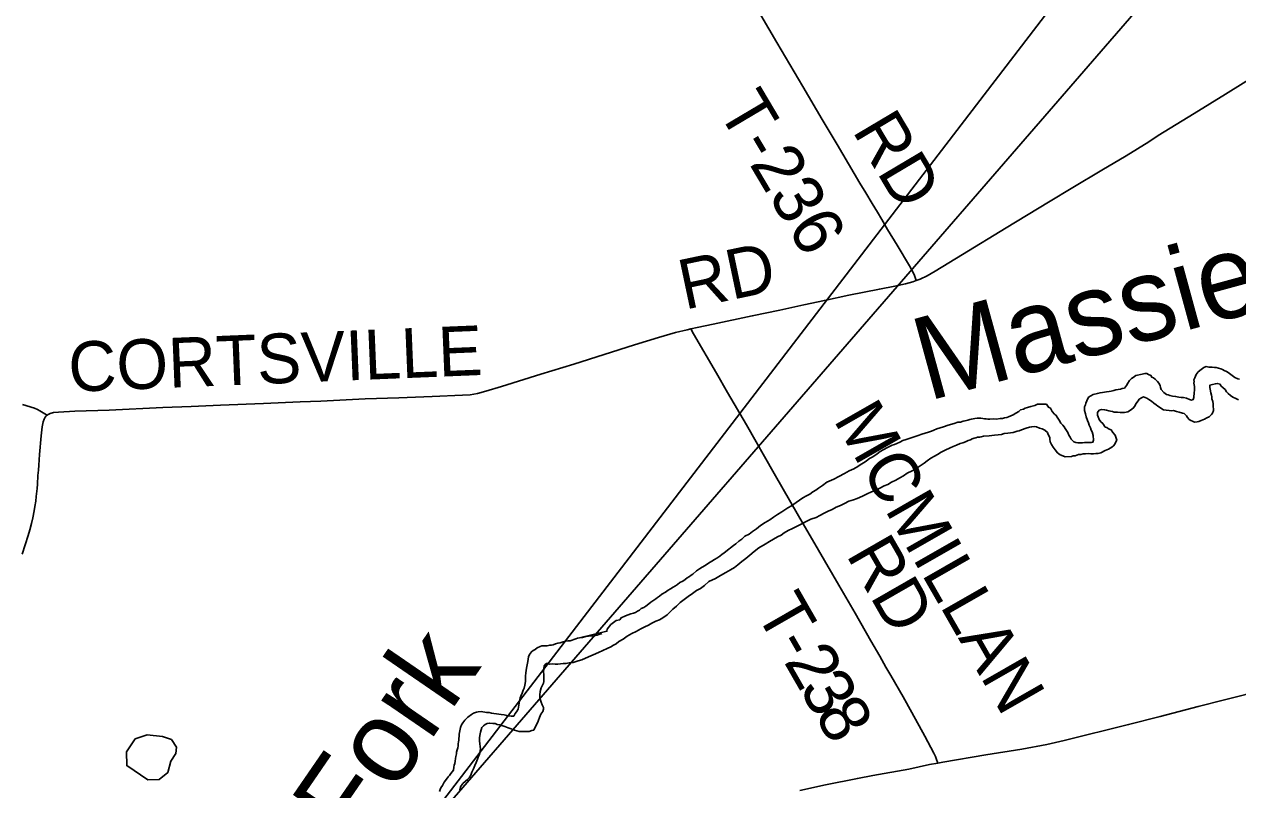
# Model space of a CAD drawing. Extents: x -19.5 to 44.1, y 0 to 22.
# Drawn here: x 5.315 to 6.7, y 19.626 to 20.5 of the extents above; entities that cross this region are included whole.
import ezdxf

# ---------------------------------------------------------------- set-up
doc = ezdxf.new("R2010")
doc.units = 0
for name, color, linetype in [('GM_X_County_Road', 7, 'Continuous'), ('GM_X_County_Road_Text', 7, 'Continuous'), ('GM_X_Minor_Lake', 7, 'Continuous'), ('GM_X_Minor_River', 7, 'Continuous'), ('GM_X_Minor_River_Text', 7, 'Continuous'), ('GM_X_Township_Road', 7, 'Continuous'), ('GM_X_Township_Road_Text', 7, 'Continuous'), ('GM_X_US_Route', 7, 'Continuous'), ('SH_Text', 7, 'Continuous')]:
    doc.layers.add(name, color=color, linetype=linetype)

msp = doc.modelspace()

# ---------------------------------------------------------------- linework, layer by layer
at = {"layer": 'GM_X_County_Road'}
for points in [[(6.3333, 20.2074), (6.338, 20.2091), (6.3458, 20.2128), (6.3549, 20.218), (6.3861, 20.2373), (6.436, 20.2676), (6.4844, 20.297), (6.5121, 20.3135), (6.5452, 20.3333), (6.5729, 20.3499), (6.5987, 20.366), (6.6097, 20.3729), (6.6505, 20.398), (6.6864, 20.4202), (6.7406, 20.4542)], [(6.076, 20.1522), (6.0834, 20.154), (6.1017, 20.1578), (6.1461, 20.167), (6.1776, 20.1737), (6.2049, 20.1797), (6.2286, 20.1848), (6.2566, 20.1906), (6.2913, 20.1976), (6.309, 20.2011), (6.3211, 20.2035), (6.3294, 20.2059), (6.3333, 20.2074)], [(5.3413, 20.0537), (5.3425, 20.0546), (5.3449, 20.0557), (5.3487, 20.0567), (5.3544, 20.0573), (5.373, 20.0582), (5.4121, 20.0596), (5.4736, 20.0624), (5.5059, 20.0637), (5.5394, 20.0651), (5.5884, 20.0672), (5.63, 20.069), (5.6536, 20.0699), (5.7044, 20.0723), (5.7429, 20.0735), (5.7808, 20.0751), (5.8155, 20.0764), (5.8241, 20.0771), (5.8326, 20.0786), (5.8422, 20.081), (5.86, 20.0863), (5.905, 20.1005), (5.9424, 20.112), (6.0117, 20.1339), (6.039, 20.1425), (6.0587, 20.148), (6.0719, 20.1513), (6.076, 20.1522)], [(5.3413, 20.0537), (5.3388, 20.0552), (5.3331, 20.0586), (5.3304, 20.0602), (5.3268, 20.0618), (5.3132, 20.0659)], [(5.3127, 19.8951), (5.3198, 19.9163), (5.3217, 19.9228), (5.3236, 19.93), (5.3251, 19.9366), (5.3266, 19.9444), (5.3274, 19.9493), (5.3283, 19.9554), (5.3288, 19.9609), (5.3298, 19.9701), (5.3302, 19.975), (5.3309, 19.9849), (5.3315, 19.991), (5.3318, 19.9966), (5.3323, 20.0027), (5.3326, 20.0089), (5.3345, 20.03), (5.3356, 20.0405), (5.3367, 20.0461), (5.3378, 20.0492), (5.3391, 20.0515), (5.3404, 20.053), (5.3413, 20.0537)]]:
    msp.add_lwpolyline(points, dxfattribs=at)
at = {"layer": 'GM_X_Minor_Lake'}
for points in [[(5.4556, 19.6888), (5.4419, 19.6841), (5.4321, 19.6695), (5.4322, 19.6536), (5.4562, 19.6375), (5.4691, 19.6376), (5.4791, 19.6458), (5.4824, 19.6586), (5.4882, 19.6673), (5.4891, 19.6748), (5.4832, 19.6833)], [(5.4832, 19.6833), (5.4731, 19.687), (5.4556, 19.6888)]]:
    msp.add_lwpolyline(points, dxfattribs=at)
at = {"layer": 'GM_X_Minor_River'}
for points in [[(6.5711, 20.0847), (6.5734, 20.0877), (6.5749, 20.0903), (6.5769, 20.0933), (6.5792, 20.0956), (6.5811, 20.0967), (6.5841, 20.0989), (6.5914, 20.1007), (6.5944, 20.1014), (6.5967, 20.1014), (6.5986, 20.1002), (6.6012, 20.099), (6.6023, 20.0971), (6.6042, 20.0963), (6.6061, 20.0948), (6.6087, 20.0921), (6.6102, 20.0902), (6.6117, 20.0875), (6.6121, 20.0852), (6.6128, 20.0829), (6.6158, 20.0798), (6.6192, 20.0775), (6.6211, 20.0771), (6.623, 20.0763), (6.626, 20.0755), (6.6294, 20.0751), (6.6332, 20.0743), (6.6358, 20.0739), (6.6385, 20.0738), (6.6419, 20.073), (6.6453, 20.0718), (6.6476, 20.071), (6.6495, 20.0718), (6.6503, 20.074), (6.6507, 20.0797), (6.6511, 20.082), (6.6508, 20.0843), (6.6508, 20.0866), (6.6501, 20.0904), (6.6505, 20.0923), (6.6501, 20.0942), (6.6513, 20.0964), (6.6529, 20.1002), (6.6552, 20.1032), (6.6586, 20.1058), (6.6617, 20.1081), (6.6644, 20.1092), (6.6674, 20.1087), (6.6712, 20.1087), (6.6739, 20.1083), (6.6758, 20.1082), (6.6784, 20.1074), (6.6811, 20.1066), (6.6829, 20.1059), (6.6848, 20.1047), (6.6875, 20.1035), (6.6893, 20.1023), (6.6969, 20.0969), (6.7003, 20.0953), (6.7022, 20.0949)], [(6.3434, 20.0332), (6.3472, 20.0343), (6.3506, 20.0354), (6.3533, 20.0365), (6.3567, 20.038), (6.3605, 20.0391), (6.3644, 20.0405), (6.3697, 20.0423), (6.3765, 20.0441), (6.3807, 20.0456), (6.3838, 20.0459), (6.3868, 20.0467), (6.3891, 20.0474), (6.3922, 20.0481), (6.3944, 20.0488), (6.3964, 20.0492), (6.3983, 20.0495), (6.4002, 20.0499), (6.4028, 20.0502), (6.407, 20.0502), (6.4093, 20.0501), (6.4112, 20.0497), (6.4131, 20.0497), (6.415, 20.0493), (6.4172, 20.0493), (6.421, 20.0496), (6.4248, 20.0491), (6.429, 20.0498), (6.4317, 20.0498), (6.4343, 20.0505), (6.4366, 20.0509), (6.4385, 20.052), (6.4412, 20.0531), (6.4439, 20.0542), (6.4469, 20.0561), (6.4504, 20.0579), (6.4523, 20.0598), (6.4557, 20.0605), (6.4576, 20.0616), (6.4603, 20.0623), (6.4641, 20.0638), (6.4687, 20.0649), (6.4717, 20.0663), (6.4755, 20.0663), (6.4793, 20.0662), (6.482, 20.0662), (6.4842, 20.0627), (6.4865, 20.0616), (6.4887, 20.0581), (6.491, 20.055), (6.4932, 20.0535), (6.4943, 20.0516), (6.4966, 20.0481), (6.4984, 20.0447), (6.5007, 20.0424), (6.5022, 20.0404), (6.5033, 20.0385), (6.5063, 20.0339), (6.5077, 20.0309), (6.5092, 20.0286), (6.5103, 20.0263), (6.5133, 20.0232), (6.5156, 20.0224), (6.5179, 20.022), (6.5209, 20.0223), (6.5232, 20.0223), (6.5255, 20.0226), (6.5285, 20.0226), (6.5308, 20.0225), (6.5331, 20.0225), (6.535, 20.0229), (6.5358, 20.0251), (6.5355, 20.0305), (6.534, 20.0347), (6.5329, 20.0366), (6.5321, 20.0392), (6.5307, 20.0423), (6.5299, 20.045), (6.5288, 20.0477), (6.5274, 20.0519), (6.5266, 20.0553), (6.5256, 20.0591), (6.5256, 20.0614), (6.5256, 20.0633), (6.5264, 20.0655), (6.5268, 20.0674), (6.528, 20.0701), (6.5299, 20.0742), (6.5353, 20.0772), (6.5402, 20.0786), (6.5433, 20.0794), (6.5459, 20.0797), (6.5505, 20.0804), (6.5535, 20.0807), (6.5558, 20.0811), (6.5589, 20.0818), (6.5612, 20.0825), (6.5638, 20.0829), (6.5665, 20.0836), (6.5684, 20.0843), (6.5711, 20.0847)], [(6.6541, 20.0462), (6.656, 20.0466), (6.6587, 20.0477), (6.6606, 20.0484), (6.6625, 20.0492), (6.6652, 20.0506), (6.6678, 20.0517), (6.6705, 20.0544), (6.6717, 20.0562), (6.6725, 20.0589), (6.6725, 20.0608), (6.6722, 20.0631), (6.6722, 20.0665), (6.6719, 20.0695), (6.6707, 20.0722), (6.6708, 20.0745), (6.6704, 20.0764), (6.6697, 20.0794), (6.669, 20.0833), (6.6683, 20.0852), (6.6683, 20.0878), (6.6717, 20.0889), (6.6748, 20.0896), (6.677, 20.09), (6.6801, 20.0892), (6.6812, 20.0873), (6.6838, 20.0849), (6.6861, 20.083), (6.6876, 20.0803), (6.6894, 20.0784), (6.6921, 20.0761), (6.6947, 20.0741), (6.6981, 20.0726), (6.7011, 20.0714)], [(6.441, 20.0337), (6.444, 20.0341), (6.4486, 20.0355), (6.4509, 20.0359), (6.4535, 20.037), (6.4589, 20.0388), (6.4627, 20.0399), (6.4653, 20.0406), (6.468, 20.0409), (6.4707, 20.0405), (6.4741, 20.0389), (6.4771, 20.0381), (6.4801, 20.0366), (6.4831, 20.0339), (6.4838, 20.0316), (6.4857, 20.0281), (6.486, 20.0262), (6.4864, 20.0232), (6.4879, 20.0201), (6.4897, 20.0171), (6.492, 20.014), (6.4946, 20.0109), (6.4976, 20.0086), (6.5006, 20.0074), (6.5033, 20.0062), (6.5105, 20.0065), (6.5124, 20.0072), (6.5147, 20.0072), (6.5185, 20.0087), (6.5211, 20.009), (6.5238, 20.0097), (6.5265, 20.0097), (6.5295, 20.01), (6.5325, 20.0096), (6.5356, 20.0096), (6.5382, 20.0099), (6.5409, 20.0099), (6.5439, 20.0106), (6.5489, 20.0132), (6.5527, 20.015), (6.5565, 20.0172), (6.5585, 20.0187), (6.56, 20.0206), (6.5612, 20.0232), (6.5623, 20.0251), (6.5605, 20.0309), (6.5579, 20.0339), (6.5557, 20.037), (6.553, 20.0382), (6.5511, 20.0397), (6.5492, 20.0401), (6.5463, 20.0444), (6.544, 20.0463), (6.5421, 20.0486), (6.541, 20.052), (6.5403, 20.0539), (6.5403, 20.0566), (6.5423, 20.0596), (6.5449, 20.0603), (6.5483, 20.0599), (6.5506, 20.0595), (6.5533, 20.0587), (6.5552, 20.0583), (6.5574, 20.0579), (6.5593, 20.0571), (6.5631, 20.057), (6.5662, 20.0566), (6.5684, 20.0566), (6.5711, 20.0569), (6.573, 20.0573), (6.5749, 20.0576), (6.578, 20.0595), (6.5814, 20.0621), (6.5833, 20.0647), (6.5841, 20.0666), (6.5868, 20.07), (6.588, 20.0719), (6.5903, 20.0737), (6.5929, 20.0745), (6.5967, 20.0733), (6.599, 20.0717), (6.602, 20.0698), (6.6046, 20.0675), (6.6073, 20.0655), (6.6091, 20.064), (6.6155, 20.0597), (6.6186, 20.0593), (6.622, 20.0589), (6.6243, 20.0588), (6.6269, 20.0592), (6.6303, 20.058), (6.6334, 20.0572), (6.6371, 20.056), (6.639, 20.0556), (6.642, 20.0529), (6.6431, 20.0509), (6.645, 20.0486), (6.6469, 20.0475), (6.6488, 20.0467), (6.6511, 20.0459), (6.6541, 20.0462)], [(5.949, 19.7995), (5.9803, 19.807), (5.9807, 19.8093), (5.9849, 19.8146), (5.991, 19.8194), (5.9949, 19.8201), (5.9964, 19.8224), (6.0017, 19.8246), (6.0075, 19.8268), (6.0105, 19.8275), (6.0128, 19.8286), (6.0151, 19.8301), (6.0174, 19.8312), (6.0193, 19.8331), (6.0224, 19.8342), (6.0247, 19.8357), (6.0281, 19.8383), (6.0304, 19.8401), (6.0327, 19.8416), (6.0362, 19.8442), (6.0381, 19.8457), (6.0404, 19.8472), (6.0431, 19.8495), (6.0473, 19.8517), (6.0503, 19.8539), (6.053, 19.8554), (6.0561, 19.8572), (6.0587, 19.8587), (6.061, 19.8602), (6.0637, 19.8625), (6.0668, 19.8643), (6.0695, 19.8662), (6.0718, 19.868), (6.0744, 19.8695), (6.0764, 19.871), (6.0783, 19.8721), (6.0825, 19.8759), (6.0859, 19.8781), (6.089, 19.88), (6.0924, 19.8822), (6.0963, 19.8848), (6.1001, 19.887), (6.1032, 19.8889), (6.1058, 19.8903), (6.1093, 19.8926), (6.112, 19.8952), (6.1139, 19.8963), (6.1162, 19.8982), (6.1246, 19.9049), (6.1273, 19.9068), (6.1308, 19.9097), (6.1342, 19.912), (6.1377, 19.9157), (6.1426, 19.9179), (6.1465, 19.9209), (6.151, 19.9239), (6.1557, 19.9276), (6.161, 19.9313), (6.1664, 19.9343), (6.1706, 19.9373), (6.1752, 19.9403), (6.1798, 19.9432), (6.1832, 19.9455), (6.1867, 19.9481), (6.1909, 19.9503), (6.1935, 19.9522), (6.1962, 19.954), (6.2001, 19.9566), (6.2039, 19.9592), (6.2081, 19.9615), (6.2119, 19.9637), (6.2154, 19.9663), (6.2188, 19.9681), (6.2219, 19.9704), (6.2265, 19.9733), (6.2314, 19.9771), (6.2395, 19.9808), (6.2452, 19.9837), (6.2513, 19.987), (6.257, 19.99), (6.262, 19.9926), (6.2666, 19.9952), (6.2704, 19.9978), (6.2739, 19.9996), (6.2765, 20.0015), (6.28, 20.0041), (6.2838, 20.0063), (6.2888, 20.0097), (6.2922, 20.0123), (6.2965, 20.0145), (6.2999, 20.0164), (6.3029, 20.0178), (6.306, 20.0193), (6.3087, 20.0204), (6.3113, 20.0215), (6.3148, 20.023), (6.3182, 20.0248), (6.322, 20.0259), (6.3354, 20.0307), (6.3396, 20.0321), (6.3434, 20.0332)], [(5.9988, 19.798), (6.0033, 19.8014), (6.0087, 19.8043), (6.0137, 19.8069), (6.019, 19.8099), (6.0236, 19.8121), (6.0278, 19.814), (6.0316, 19.8162), (6.0362, 19.8184), (6.0404, 19.8202), (6.0442, 19.8225), (6.0492, 19.8258), (6.0523, 19.8288), (6.0557, 19.8322), (6.0596, 19.8355), (6.0638, 19.8397), (6.0684, 19.8434), (6.073, 19.8467), (6.078, 19.8501), (6.0826, 19.8534), (6.0872, 19.856), (6.0918, 19.8594), (6.0968, 19.8639), (6.1044, 19.8672), (6.1101, 19.8705), (6.1159, 19.8739), (6.1212, 19.8772), (6.1258, 19.8798), (6.1297, 19.8828), (6.1343, 19.8865), (6.1389, 19.8902), (6.1435, 19.894), (6.1484, 19.8981), (6.1538, 19.9022), (6.1611, 19.9066), (6.1657, 19.9096), (6.1703, 19.9122), (6.1752, 19.9148), (6.1791, 19.9167), (6.1825, 19.9193), (6.1871, 19.9219), (6.1921, 19.9244), (6.1974, 19.927), (6.2131, 19.9348), (6.2192, 19.937), (6.2234, 19.9392), (6.2283, 19.9418), (6.2329, 19.944), (6.2375, 19.9462), (6.2421, 19.9488), (6.2471, 19.9506), (6.2516, 19.9528), (6.2566, 19.9554), (6.2616, 19.9569), (6.2658, 19.9587), (6.2722, 19.9613), (6.2772, 19.9639), (6.2822, 19.9661), (6.2868, 19.9679), (6.2917, 19.9705), (6.2967, 19.9731), (6.3009, 19.9746), (6.3051, 19.9772), (6.3101, 19.9797), (6.3146, 19.982), (6.3189, 19.9846), (6.3231, 19.9875), (6.3288, 19.9901), (6.3322, 19.992), (6.3357, 19.9942), (6.3391, 19.9968), (6.3426, 19.999), (6.346, 20.0016), (6.3502, 20.0046), (6.3541, 20.0068), (6.3575, 20.0087), (6.3617, 20.0113), (6.3663, 20.0139), (6.372, 20.0165), (6.3755, 20.0179), (6.3793, 20.0194), (6.3835, 20.0212), (6.3865, 20.022), (6.3896, 20.0234), (6.3926, 20.0249), (6.3953, 20.0256), (6.3972, 20.0267), (6.3995, 20.0275), (6.4014, 20.0278), (6.4033, 20.0286), (6.4056, 20.0285), (6.4075, 20.0289), (6.4102, 20.0296), (6.4166, 20.0303), (6.4197, 20.0306), (6.4227, 20.0309), (6.4269, 20.0313), (6.4307, 20.0316), (6.4337, 20.0327), (6.4379, 20.033), (6.441, 20.0337)], [(5.7893, 19.624), (5.7901, 19.6262), (5.7909, 19.6281), (5.7928, 19.6308), (5.7947, 19.6345), (5.7971, 19.6383), (5.799, 19.6406), (5.8005, 19.6424), (5.8021, 19.6447), (5.8036, 19.6466), (5.8052, 19.6484), (5.8056, 19.6519), (5.806, 19.6541), (5.8068, 19.656), (5.8072, 19.6587), (5.8076, 19.6617), (5.808, 19.664), (5.8088, 19.667), (5.8088, 19.6689), (5.8092, 19.6716), (5.81, 19.6738), (5.8104, 19.6761), (5.8105, 19.6784), (5.8109, 19.6807), (5.8113, 19.6826), (5.8113, 19.6848), (5.8117, 19.6867), (5.8117, 19.6894), (5.8121, 19.6913), (5.8125, 19.6932), (5.813, 19.697), (5.8142, 19.7), (5.8157, 19.7026), (5.818, 19.7056), (5.8215, 19.709), (5.8257, 19.712), (5.828, 19.7135), (5.8314, 19.7146), (5.8333, 19.7149), (5.8367, 19.7152), (5.8428, 19.7144), (5.8458, 19.7144), (5.8485, 19.7136), (5.8511, 19.7131), (5.8542, 19.7127), (5.8568, 19.7123), (5.8595, 19.7119), (5.8629, 19.7115), (5.8659, 19.7107), (5.8678, 19.7106), (5.8709, 19.7102), (5.8739, 19.7102), (5.8754, 19.7132), (5.877, 19.7151), (5.8789, 19.7181), (5.8797, 19.7226), (5.8806, 19.7272), (5.8814, 19.7309), (5.8821, 19.7328), (5.8837, 19.7362), (5.8849, 19.7396), (5.8857, 19.7419), (5.8865, 19.7453), (5.8869, 19.7472), (5.8873, 19.7502), (5.8873, 19.7529), (5.8874, 19.7559), (5.8878, 19.7594), (5.8882, 19.762), (5.8886, 19.765), (5.8899, 19.7726), (5.8903, 19.7753), (5.8907, 19.7779), (5.8919, 19.7806), (5.8942, 19.7836), (5.8961, 19.7851), (5.8984, 19.7862), (5.9007, 19.788), (5.9041, 19.7895), (5.906, 19.7902), (5.9091, 19.7902), (5.9121, 19.7905), (5.9151, 19.7913), (5.917, 19.7912), (5.9189, 19.7916), (5.9216, 19.7927), (5.9243, 19.7934), (5.9269, 19.7937), (5.9304, 19.7948), (5.933, 19.7956), (5.9357, 19.7959), (5.9384, 19.7962), (5.9407, 19.797), (5.9426, 19.7977), (5.9448, 19.7984), (5.9468, 19.7992), (5.949, 19.7995)], [(5.8125, 19.6259), (5.8133, 19.6293), (5.816, 19.6331), (5.8187, 19.6357), (5.8213, 19.6376), (5.8229, 19.6398), (5.8248, 19.6428), (5.826, 19.6462), (5.828, 19.65), (5.8295, 19.6538), (5.8311, 19.6572), (5.8326, 19.661), (5.8338, 19.6644), (5.835, 19.6663), (5.8362, 19.6727), (5.8355, 19.6754), (5.8351, 19.6784), (5.8348, 19.6818), (5.8349, 19.6853), (5.8353, 19.6879), (5.8361, 19.6917), (5.8369, 19.6943), (5.8377, 19.697), (5.8396, 19.6989), (5.8415, 19.7007), (5.8438, 19.7018), (5.8461, 19.7022), (5.8502, 19.7018), (5.8529, 19.7017), (5.8552, 19.7005), (5.8582, 19.7001), (5.8616, 19.6989), (5.8639, 19.6981), (5.8658, 19.6974), (5.8676, 19.6966), (5.871, 19.6954), (5.8748, 19.6942), (5.8775, 19.6934), (5.8801, 19.6926), (5.8835, 19.6925), (5.8866, 19.6925), (5.8896, 19.6925), (5.8915, 19.6924), (5.8946, 19.6935), (5.8968, 19.6942), (5.8976, 19.6961), (5.9015, 19.7033), (5.9023, 19.7056), (5.9035, 19.7086), (5.905, 19.7124), (5.907, 19.7154), (5.9078, 19.718), (5.9078, 19.7199), (5.9063, 19.723), (5.9052, 19.726), (5.9038, 19.7306), (5.9038, 19.7344), (5.9042, 19.7382), (5.9054, 19.7424), (5.9066, 19.7454), (5.9078, 19.7477), (5.9082, 19.7496), (5.9082, 19.7534), (5.9082, 19.756), (5.9083, 19.7579), (5.9079, 19.7602), (5.9084, 19.7644), (5.9088, 19.7674), (5.9111, 19.77), (5.913, 19.77), (5.9153, 19.7696), (5.9183, 19.7699), (5.9213, 19.7695), (5.9244, 19.7695), (5.9274, 19.7698), (5.9304, 19.7701), (5.9335, 19.7701), (5.9373, 19.7708), (5.9419, 19.7715), (5.9476, 19.7733), (5.9518, 19.7744), (5.956, 19.7762), (5.9708, 19.7829), (5.9758, 19.7851), (5.9804, 19.7873), (5.9846, 19.7891), (5.9877, 19.791), (5.9907, 19.7928), (5.9938, 19.7954), (5.9988, 19.798)], [(5.949, 19.7995), (5.9525, 19.7998), (5.9551, 19.8006), (5.9574, 19.8013), (5.9593, 19.8013), (5.9654, 19.8019), (5.9673, 19.8023), (5.9692, 19.8026), (5.9711, 19.8034), (5.9738, 19.8041), (5.9746, 19.8044)]]:
    msp.add_lwpolyline(points, dxfattribs=at)
at = {"layer": 'GM_X_Township_Road'}
for points in [[(6.3333, 20.2074), (6.3326, 20.2096), (6.3314, 20.2133), (6.3298, 20.2166), (6.3256, 20.2244), (6.3115, 20.2478), (6.3004, 20.2657), (6.2941, 20.2771), (6.2891, 20.2857), (6.283, 20.2956), (6.2757, 20.3077), (6.2688, 20.3187), (6.243, 20.3626), (6.226, 20.3914), (6.2039, 20.429), (6.1744, 20.4793), (6.1561, 20.5104)], [(6.358, 19.6564), (6.3561, 19.6616), (6.3552, 19.6639), (6.3535, 19.6679), (6.3433, 19.6871), (6.3284, 19.7143), (6.3184, 19.7322), (6.3044, 19.7564), (6.2988, 19.766), (6.2919, 19.7785), (6.2815, 19.7962), (6.2637, 19.8275), (6.2449, 19.8597), (6.2217, 19.8994), (6.1991, 19.9387), (6.1713, 19.9871), (6.1395, 20.0426), (6.1181, 20.0797), (6.1052, 20.1017), (6.0792, 20.1467), (6.076, 20.1522)]]:
    msp.add_lwpolyline(points, dxfattribs=at)
at = {"layer": 'GM_X_US_Route'}
msp.add_lwpolyline([(6.2006, 19.6252), (6.2297, 19.6316), (6.2662, 19.6389), (6.2839, 19.6423), (6.3249, 19.6497), (6.3486, 19.6547), (6.358, 19.6564), (6.3638, 19.6574), (6.4128, 19.6658), (6.4539, 19.6725), (6.4826, 19.6778), (6.5021, 19.6821), (6.5757, 19.7004), (6.6118, 19.7097), (6.6551, 19.7209), (6.6852, 19.7286), (6.7322, 19.7404)], dxfattribs=at)
at = {"layer": 'SH_Text'}
msp.add_lwpolyline([(7.0453, 21.0473), (5.7192, 19.517), (7.0453, 21.2473)], close=True, dxfattribs=at)

# ---------------------------------------------------------------- texts
at = {"layer": 'GM_X_County_Road_Text'}
for s, rotation, p in [('RD', 11.8887, (6.069, 20.174)), ('CORTSVILLE', 2.3487, (5.3667, 20.0803))]:
    msp.add_text(s, height=0.05682, rotation=rotation, dxfattribs=at).set_placement(p)
at = {"layer": 'GM_X_Minor_River_Text'}
for s, height, rotation, p in [('Massies', 0.09469, 15.2703, (6.3464, 20.0696)), ('Fork', 0.09468, 55.5067, (5.6941, 19.558))]:
    msp.add_text(s, height=height, rotation=rotation, dxfattribs=at).set_placement(p)
at = {"layer": 'GM_X_Township_Road_Text'}
for s, height, rotation, p in [('T-236', 0.05682, 300.6792, (6.1057, 20.4025)), ('RD', 0.05682, 300.7072, (6.2597, 20.3787)), ('MCMILLAN', 0.05682, 299.7763, (6.2382, 20.0487)), ('RD', 0.05682, 299.8675, (6.2526, 19.8946)), ('T', 0.0568, 299.848, (6.1488, 19.8296)), ('2', 0.0568, 299.8638, (6.1816, 19.7725)), ('-', 0.0568, 299.8446, (6.17, 19.7927)), ('3', 0.0568, 299.9083, (6.199, 19.7421)), ('8', 0.0568, 300.1036, (6.2166, 19.7116))]:
    msp.add_text(s, height=height, rotation=rotation, dxfattribs=at).set_placement(p)

doc.saveas('drawing.dxf')
